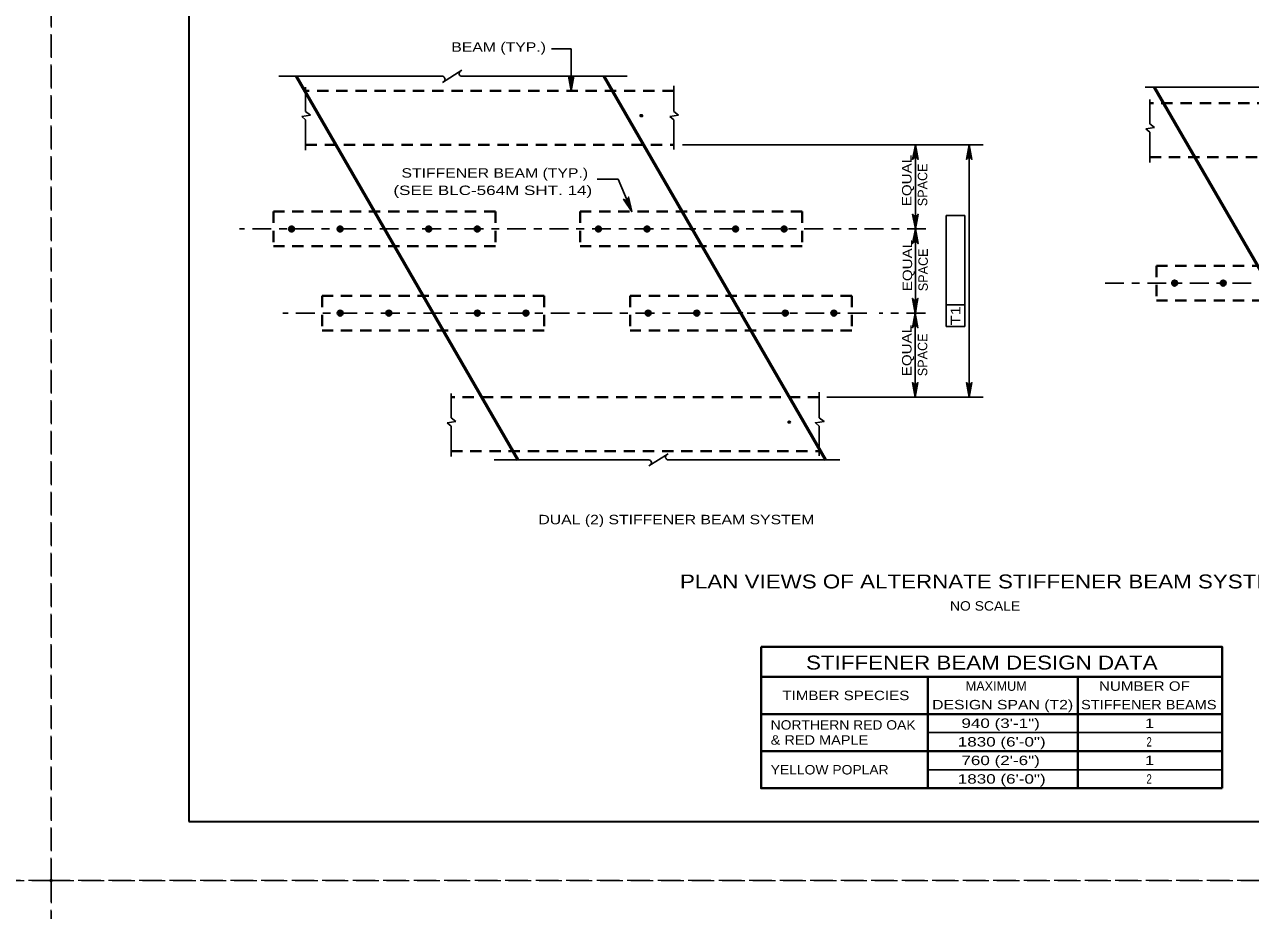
# Model space of a CAD drawing. Extents: x -11 to 79, y -154 to 0.
# Drawn here: x 33.66 to 49.26, y -132.38 to -121.11 of the extents above; entities that cross this region are included whole.
import ezdxf
from ezdxf.enums import TextEntityAlignment as Align

# ---------------------------------------------------------------- set-up
doc = ezdxf.new("R2010")
doc.units = 0
doc.header["$LTSCALE"] = 0.048
doc.header["$PDMODE"] = 32
doc.header["$PDSIZE"] = 0.024
for name, pattern in [('DOT_DASHED', [7.7, 5, -1.2, 0.3, -1.2]), ('LONG_DASHED', [7.5, 6, -1.5]), ('MEDIUM_DASHED', [4.5, 3, -1.5])]:
    doc.linetypes.add(name, pattern=pattern)
for name, color, linetype, lineweight in [('1', 7, 'Continuous', 25), ('10', 7, 'Continuous', 40), ('2', 7, 'Continuous', 35), ('3', 7, 'Continuous', 25), ('4', 7, 'Continuous', 25), ('63', 7, 'LONG_DASHED', 13), ('8', 7, 'Continuous', 35)]:
    doc.layers.add(name, color=color, linetype=linetype, lineweight=lineweight)
doc.layers.add('62', color=7, linetype='Continuous')

msp = doc.modelspace()

# ---------------------------------------------------------------- hatches: boundary and pattern name
at = {"layer": '4'}
for points in [[(40.61575, -121.9585), (40.61458, -121.95375), (40.617, -121.95375)], [(41.385, -123.49425), (41.38208, -123.49033), (41.38433, -123.48942)], [(45.01308, -124.6655), (44.97367, -124.6655), (44.99333, -124.78358)], [(45.0105, -124.90175), (44.97117, -124.90175), (44.99083, -124.78358)], [(45.0105, -125.73558), (44.97117, -125.73558), (44.99083, -125.85367)], [(45.6965, -125.73367), (45.6565, -125.73367), (45.6765, -125.85367)]]:
    msp.add_hatch(color=256, dxfattribs=at).paths.add_polyline_path(points)

# ---------------------------------------------------------------- linework, layer by layer
at = {"layer": '1', "lineweight": 35}
msp.add_lwpolyline([(35.75, -131.25), (67.25, -131.25), (67.25, -110.75), (35.75, -110.75)], close=True, dxfattribs=at)
at = {"layer": '10'}
for p, q in [((43.03117, -129.41033), (48.89708, -129.41033)), ((45.15033, -129.41033), (45.15033, -130.82758)), ((47.06133, -129.41033), (47.06133, -130.82758)), ((43.03117, -129.88275), (48.89708, -129.88275)), ((43.03117, -130.35517), (48.89708, -130.35517))]:
    msp.add_line(p, q, dxfattribs=at)
at = {"layer": '10', "lineweight": 25}
for p, q in [((45.15033, -130.119), (48.89708, -130.119)), ((45.15033, -130.59142), (48.89708, -130.59142))]:
    msp.add_line(p, q, dxfattribs=at)
at = {"layer": '10'}
for points in [[(43.03117, -129.02875), (43.03117, -130.82758), (48.89708, -130.82758)], [(43.03117, -129.02875), (48.89708, -129.02875), (48.89708, -130.82758)]]:
    msp.add_lwpolyline(points, dxfattribs=at)
at = {"layer": '2', "lineweight": 53}
for p, q in [((37.118, -121.77325), (39.93767, -126.65125)), ((41.03133, -121.77325), (43.851, -126.65125)), ((48.03183, -121.90983), (50.90317, -126.87733))]:
    msp.add_line(p, q, dxfattribs=at)
at = {"layer": '3'}
for p, q in [((38.97817, -121.77325), (36.89525, -121.77325)), ((39.224, -121.69583), (38.97767, -121.85067)), ((41.32825, -121.77325), (39.22683, -121.77325)), ((37.23625, -122.21992), (37.23625, -121.91092)), ((50, -121.90983), (47.91708, -121.90983)), ((37.29783, -122.2675), (37.23625, -122.21992)), ((37.1875, -122.28442), (37.29783, -122.2675)), ((37.23625, -122.32817), (37.1875, -122.28442)), ((37.23625, -122.71258), (37.23625, -122.32817)), ((41.87042, -122.28442), (41.98075, -122.2675)), ((41.91917, -122.32817), (41.87042, -122.28442)), ((41.91917, -122.70508), (41.91917, -122.32817)), ((47.926, -122.44133), (48.03633, -122.42433)), ((47.97467, -122.48508), (47.926, -122.44133)), ((47.97467, -122.86942), (47.97467, -122.48508)), ((39.087, -126.11517), (39.087, -125.80617)), ((39.14858, -126.16267), (39.087, -126.11517)), ((39.03825, -126.17967), (39.14858, -126.16267)), ((39.087, -126.22342), (39.03825, -126.17967)), ((39.087, -126.60783), (39.087, -126.22342)), ((41.84867, -126.57383), (41.60233, -126.72867)), ((41.60283, -126.65125), (39.63683, -126.65125)), ((44.03075, -126.65125), (41.8515, -126.65125))]:
    msp.add_line(p, q, dxfattribs=at)
at = {"layer": '3', "linetype": 'MEDIUM_DASHED', "lineweight": 40}
for p, q in [((41.91917, -121.9585), (37.23625, -121.9585)), ((52.65758, -122.11533), (47.97467, -122.11533)), ((37.23625, -122.64342), (41.91917, -122.64342)), ((47.97467, -122.80025), (52.65758, -122.80025)), ((43.55442, -123.49425), (43.55442, -123.93517)), ((43.55442, -123.93517), (40.73158, -123.93517)), ((40.27017, -124.56433), (37.44733, -124.56433)), ((37.44733, -124.56433), (37.44733, -125.00525)), ((40.27017, -124.56433), (40.27017, -125.00525)), ((41.364, -124.56433), (41.364, -125.00525)), ((44.18683, -124.56433), (41.364, -124.56433)), ((44.18683, -124.56433), (44.18683, -125.00525)), ((50.8835, -124.62325), (48.06067, -124.62325)), ((40.27017, -125.00525), (37.44733, -125.00525)), ((44.18683, -125.00525), (41.364, -125.00525)), ((43.76992, -125.85367), (39.087, -125.85367)), ((39.087, -126.53867), (43.76992, -126.53867))]:
    msp.add_line(p, q, dxfattribs=at)
at = {"layer": '3'}
for points in [[(41.98075, -122.2675), (41.91917, -122.21992), (41.91917, -121.896)], [(48.03633, -122.42433), (47.97467, -122.37675), (47.97467, -122.06775)], [(43.76992, -126.60033), (43.76992, -126.22342), (43.72117, -126.17967), (43.8315, -126.16267), (43.76992, -126.11517), (43.76992, -125.79117)]]:
    msp.add_lwpolyline(points, dxfattribs=at)
at = {"layer": '3', "linetype": 'MEDIUM_DASHED', "lineweight": 40}
for points in [[(39.65092, -123.49425), (39.65092, -123.93517), (36.82808, -123.93517)], [(39.65092, -123.49425), (36.82808, -123.49425), (36.82808, -123.93517)], [(43.55442, -123.49425), (40.73158, -123.49425), (40.73158, -123.93517)], [(50.8835, -124.18225), (48.06067, -124.18225), (48.06067, -124.62325)]]:
    msp.add_lwpolyline(points, dxfattribs=at)
at = {"layer": '3', "lineweight": 40}
for centre, radius in [((37.05842, -123.71471), 0.03333), ((37.05842, -123.71471), 0.025), ((37.05842, -123.71471), 0.01667), ((37.05842, -123.71471), 0.00833), ((37.67653, -123.71471), 0.03333), ((37.67653, -123.71471), 0.025), ((37.67653, -123.71471), 0.01667), ((37.67653, -123.71471), 0.00833), ((38.80251, -123.71471), 0.03333), ((38.80251, -123.71471), 0.025), ((38.80251, -123.71471), 0.01667), ((38.80251, -123.71471), 0.00833), ((39.42062, -123.71471), 0.03333), ((39.42062, -123.71471), 0.025), ((39.42062, -123.71471), 0.01667), ((39.42062, -123.71471), 0.00833), ((40.96189, -123.71471), 0.03333), ((40.96189, -123.71471), 0.025), ((40.96189, -123.71471), 0.01667), ((40.96189, -123.71471), 0.00833), ((41.58, -123.71471), 0.03333), ((41.58, -123.71471), 0.025), ((41.58, -123.71471), 0.01667), ((41.58, -123.71471), 0.00833), ((42.70598, -123.71471), 0.03333), ((42.70598, -123.71471), 0.025), ((42.70598, -123.71471), 0.01667), ((42.70598, -123.71471), 0.00833), ((43.32409, -123.71471), 0.03333), ((43.32409, -123.71471), 0.025), ((43.32409, -123.71471), 0.01667), ((43.32409, -123.71471), 0.00833), ((48.29098, -124.40274), 0.03333), ((48.29098, -124.40274), 0.025), ((48.29098, -124.40274), 0.01667), ((48.29098, -124.40274), 0.00833), ((48.90909, -124.40274), 0.03333), ((48.90909, -124.40274), 0.025), ((48.90909, -124.40274), 0.01667), ((48.90909, -124.40274), 0.00833), ((37.67765, -124.78479), 0.03333), ((37.67765, -124.78479), 0.025), ((37.67765, -124.78479), 0.01667), ((37.67765, -124.78479), 0.00833), ((38.29576, -124.78479), 0.03333), ((38.29576, -124.78479), 0.025), ((38.29576, -124.78479), 0.01667), ((38.29576, -124.78479), 0.00833), ((39.42174, -124.78479), 0.03333), ((39.42174, -124.78479), 0.025), ((39.42174, -124.78479), 0.01667), ((39.42174, -124.78479), 0.00833), ((40.03985, -124.78479), 0.03333), ((40.03985, -124.78479), 0.025), ((40.03985, -124.78479), 0.01667), ((40.03985, -124.78479), 0.00833), ((41.59428, -124.78479), 0.03333), ((41.59428, -124.78479), 0.025), ((41.59428, -124.78479), 0.01667), ((41.59428, -124.78479), 0.00833), ((42.21239, -124.78479), 0.03333), ((42.21239, -124.78479), 0.025), ((42.21239, -124.78479), 0.01667), ((42.21239, -124.78479), 0.00833), ((43.33837, -124.78479), 0.03333), ((43.33837, -124.78479), 0.025), ((43.33837, -124.78479), 0.01667), ((43.33837, -124.78479), 0.00833), ((43.95648, -124.78479), 0.03333), ((43.95648, -124.78479), 0.025), ((43.95648, -124.78479), 0.01667), ((43.95648, -124.78479), 0.00833)]:
    msp.add_circle(centre, radius, dxfattribs=at)
at = {"layer": '3'}
for centre in [(37.05842, -123.71471), (37.67653, -123.71471), (38.80251, -123.71471), (39.42062, -123.71471), (40.96189, -123.71471), (41.58, -123.71471), (42.70598, -123.71471), (43.32409, -123.71471), (48.29098, -124.40274), (48.90909, -124.40274), (37.67765, -124.78479), (38.29576, -124.78479), (39.42174, -124.78479), (40.03985, -124.78479), (41.59428, -124.78479), (42.21239, -124.78479), (43.33837, -124.78479), (43.95648, -124.78479)]:
    msp.add_circle(centre, 0.02953, dxfattribs=at)
for centre, start, end in [((38.97478, -121.80943), 302.13276, 84.67141), ((39.22681, -121.73685), 120, 270), ((41.85149, -126.6149), 120, 270), ((41.59946, -126.68748), 302.13276, 84.67141)]:
    msp.add_arc(centre, 0.03637, start, end, dxfattribs=at)
for p in [(42.14642, -123.7135), (42.77883, -124.78358)]:
    msp.add_point(p, dxfattribs=at)
at = {"layer": '4'}
for p, q in [((40.61575, -121.425), (40.36567, -121.425)), ((40.61575, -121.9585), (40.61575, -121.425)), ((42.03167, -122.64342), (45.43908, -122.64342)), ((44.32675, -122.64342), (45.8565, -122.64342)), ((44.47967, -122.64342), (45.08192, -122.64342)), ((44.99333, -122.64342), (44.99333, -123.7135)), ((45.6765, -122.64342), (45.6765, -125.85367)), ((41.21233, -123.08183), (40.94592, -123.08183)), ((41.385, -123.49425), (41.21233, -123.08183)), ((45.385, -123.54167), (45.62117, -123.54167)), ((45.385, -124.65483), (45.385, -123.54167)), ((45.62117, -123.54167), (45.62117, -124.95367)), ((44.99333, -123.7135), (44.99333, -124.6655)), ((45.385, -124.95367), (45.385, -124.65483)), ((45.62117, -124.67808), (45.385, -124.67808)), ((44.99083, -124.90175), (44.99083, -125.85367)), ((45.62117, -124.95367), (45.385, -124.95367)), ((43.86867, -125.85367), (45.8565, -125.85367)), ((44.7315, -125.85367), (45.0665, -125.85367))]:
    msp.add_line(p, q, dxfattribs=at)
at = {"layer": '4', "linetype": 'DOT_DASHED'}
for p, q in [((43.82033, -123.7135), (36.39458, -123.7135)), ((45.12817, -123.7135), (43.95325, -123.7135)), ((54.66533, -124.40275), (47.37417, -124.40275)), ((44.37483, -124.78483), (36.94908, -124.78483)), ((45.12058, -124.78358), (44.53333, -124.78358))]:
    msp.add_line(p, q, dxfattribs=at)
at = {"layer": '4'}
for points in [[(40.61575, -121.9585), (40.65067, -121.77208), (40.64075, -121.78642), (40.62825, -121.79383), (40.61575, -121.796), (40.60325, -121.79383), (40.59075, -121.78642), (40.58083, -121.77208), (40.61575, -121.9585), (40.59075, -121.78642), (40.60325, -121.79383), (40.61575, -121.9585), (40.61575, -121.796), (40.62825, -121.79383), (40.61575, -121.9585), (40.64075, -121.78642)], [(44.99333, -122.64342), (44.95842, -122.82983), (44.96833, -122.8155), (44.98083, -122.80808), (44.99333, -122.80592), (45.00583, -122.80808), (45.01833, -122.8155), (45.02825, -122.82983), (44.99333, -122.64342), (45.01833, -122.8155), (45.00583, -122.80808), (44.99333, -122.64342), (44.99333, -122.80592), (44.98083, -122.80808), (44.99333, -122.64342), (44.96833, -122.8155)], [(45.6765, -122.64342), (45.64158, -122.82983), (45.6515, -122.8155), (45.664, -122.80808), (45.6765, -122.80592), (45.689, -122.80808), (45.7015, -122.8155), (45.71142, -122.82983), (45.6765, -122.64342), (45.7015, -122.8155), (45.689, -122.80808), (45.6765, -122.64342), (45.6765, -122.80592), (45.664, -122.80808), (45.6765, -122.64342), (45.6515, -122.8155)], [(41.385, -123.49425), (41.34525, -123.30883), (41.34158, -123.32592), (41.33292, -123.33758), (41.32225, -123.34433), (41.30992, -123.34717), (41.2955, -123.34517), (41.28075, -123.33583), (41.385, -123.49425), (41.2955, -123.34517), (41.30992, -123.34717), (41.385, -123.49425), (41.32225, -123.34433), (41.33292, -123.33758), (41.385, -123.49425), (41.34158, -123.32592)], [(44.99333, -123.7135), (45.02825, -123.52708), (45.01833, -123.54142), (45.00583, -123.54883), (44.99333, -123.551), (44.98083, -123.54883), (44.96833, -123.54142), (44.95842, -123.52708), (44.99333, -123.7135), (44.96833, -123.54142), (44.98083, -123.54883), (44.99333, -123.7135), (44.99333, -123.551), (45.00583, -123.54883), (44.99333, -123.7135), (45.01833, -123.54142)], [(44.99333, -123.7135), (45.02825, -123.89992), (45.01833, -123.88558), (45.00583, -123.87817), (44.99333, -123.876), (44.98083, -123.87817), (44.96833, -123.88558), (44.95842, -123.89992), (44.99333, -123.7135), (44.96833, -123.88558), (44.98083, -123.87817), (44.99333, -123.7135), (44.99333, -123.876), (45.00583, -123.87817), (44.99333, -123.7135), (45.01833, -123.88558)], [(44.99083, -124.78358), (45.02575, -124.59717), (45.01583, -124.6115), (45.00333, -124.61892), (44.99083, -124.62108), (44.97833, -124.61892), (44.96583, -124.6115), (44.95592, -124.59717), (44.99083, -124.78358), (44.96583, -124.6115), (44.97833, -124.61892), (44.99083, -124.78358), (44.99083, -124.62108), (45.00333, -124.61892), (44.99083, -124.78358), (45.01583, -124.6115)], [(44.99083, -124.78358), (45.02575, -124.97), (45.01583, -124.95567), (45.00333, -124.94825), (44.99083, -124.94608), (44.97833, -124.94825), (44.96583, -124.95567), (44.95592, -124.97), (44.99083, -124.78358), (44.96583, -124.95567), (44.97833, -124.94825), (44.99083, -124.78358), (44.99083, -124.94608), (45.00333, -124.94825), (44.99083, -124.78358), (45.01583, -124.95567)], [(44.99083, -125.85367), (45.02575, -125.66725), (45.01583, -125.68158), (45.00333, -125.689), (44.99083, -125.69117), (44.97833, -125.689), (44.96583, -125.68158), (44.95592, -125.66725), (44.99083, -125.85367), (44.96583, -125.68158), (44.97833, -125.689), (44.99083, -125.85367), (44.99083, -125.69117), (45.00333, -125.689), (44.99083, -125.85367), (45.01583, -125.68158)], [(45.6765, -125.85367), (45.71142, -125.66725), (45.7015, -125.68158), (45.689, -125.689), (45.6765, -125.69117), (45.664, -125.689), (45.6515, -125.68158), (45.64158, -125.66725), (45.6765, -125.85367), (45.6515, -125.68158), (45.664, -125.689), (45.6765, -125.85367), (45.6765, -125.69117), (45.689, -125.689), (45.6765, -125.85367), (45.7015, -125.68158)]]:
    msp.add_lwpolyline(points, dxfattribs=at)
for points in [[(40.61575, -121.9585), (40.61458, -121.95375), (40.617, -121.95375)], [(41.385, -123.49425), (41.38208, -123.49033), (41.38433, -123.48942)], [(45.01308, -124.6655), (44.97367, -124.6655), (44.99333, -124.78358)], [(45.0105, -124.90175), (44.97117, -124.90175), (44.99083, -124.78358)], [(45.0105, -125.73558), (44.97117, -125.73558), (44.99083, -125.85367)], [(45.6965, -125.73367), (45.6565, -125.73367), (45.6765, -125.85367)]]:
    msp.add_lwpolyline(points, close=True, dxfattribs=at)
at = {"layer": '62'}
msp.add_point((34, -132), dxfattribs=at)
at = {"layer": '63'}
for points in [[(0, -132), (34, -132), (34, -110), (0, -110)], [(34, -132), (68, -132), (68, -110), (34, -110)], [(0, -154), (34, -154), (34, -132), (0, -132)], [(34, -154), (68, -154), (68, -132), (34, -132)]]:
    msp.add_lwpolyline(points, close=True, dxfattribs=at)
at = {"layer": '8'}
for p in [(41.50742, -122.27317), (41.50808, -122.27433), (42.14642, -123.7135), (42.77883, -124.78358), (43.39, -126.1695)]:
    msp.add_point(p, dxfattribs=at)

# ---------------------------------------------------------------- texts
at = {"layer": '4'}
for s, width, p in [('BEAM (TYP.)', 1.25, (39.0905, -121.461)), ('STIFFENER BEAM (TYP.)', 1.25, (38.45667, -123.06225)), ('(SEE BLC-564M SHT. 14)', 1.35, (38.354, -123.283)), ('NO SCALE', 1.1, (45.43392, -128.56792)), ('NORTHERN RED OAK', 1.1, (43.15267, -130.08158)), ('& RED MAPLE', 1.15, (43.15267, -130.27275)), ('YELLOW POPLAR', 1.1, (43.15267, -130.65133))]:
    msp.add_text(s, height=0.12, dxfattribs=dict(at, width=width)).set_placement(p)
at = {"layer": '4', "width": 1.3}
msp.add_text('T1', height=0.12, rotation=90, dxfattribs=at).set_placement((45.564, -124.81746), align=Align.CENTER)
at = {"layer": '4'}
for s, height, width, p in [('DUAL (2) STIFFENER BEAM SYSTEM', 0.12, 1.25, (41.95362, -127.46967)), ('PLAN VIEWS OF ALTERNATE STIFFENER BEAM SYSTEMS', 0.1772, 1.2, (45.97279, -128.28583)), ('STIFFENER BEAM DESIGN DATA', 0.1772, 1.2, (45.83833, -129.31692)), ('TIMBER SPECIES', 0.12, 1.2, (44.10846, -129.7065)), ('NUMBER OF ', 0.12, 1.2, (47.93354, -129.58742)), ('DESIGN SPAN (T2)', 0.12, 1.25, (46.10337, -129.82358)), ('STIFFENER BEAMS', 0.12, 1.15, (47.9625, -129.82358)), ('940 (3\'-1")', 0.12, 1.35, (46.07771, -130.05983)), ('1', 0.12, 1.3, (47.97187, -130.05983)), ('1830 (6\'-0")', 0.12, 1.35, (46.09158, -130.296)), ('2', 0.12, 0.75, (47.96688, -130.296)), ('760 (2\'-6")', 0.12, 1.35, (46.07771, -130.53225)), ('1', 0.12, 1.3, (47.97187, -130.53225)), ('1830 (6\'-0")', 0.12, 1.35, (46.09158, -130.7685)), ('2', 0.12, 0.75, (47.96688, -130.7685))]:
    msp.add_text(s, height=height, dxfattribs=dict(at, width=width)).set_placement(p, align=Align.CENTER)
msp.add_text('MAXIMUM', height=0.12, dxfattribs=at).set_placement((46.02158, -129.58742), align=Align.CENTER)
at = {"layer": '8', "width": 1.2}
for p in [(44.94392, -123.42542), (44.95158, -124.50625), (44.944, -125.58708)]:
    msp.add_text('EQUAL ', height=0.12, rotation=89.971, dxfattribs=at).set_placement(p)
at = {"layer": '8'}
for p in [(45.14392, -123.4255), (45.15158, -124.50633), (45.144, -125.58717)]:
    msp.add_text('SPACE', height=0.12, rotation=89.971, dxfattribs=at).set_placement(p)

doc.saveas('drawing.dxf')
